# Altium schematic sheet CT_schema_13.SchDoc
size 389 x 385 mm
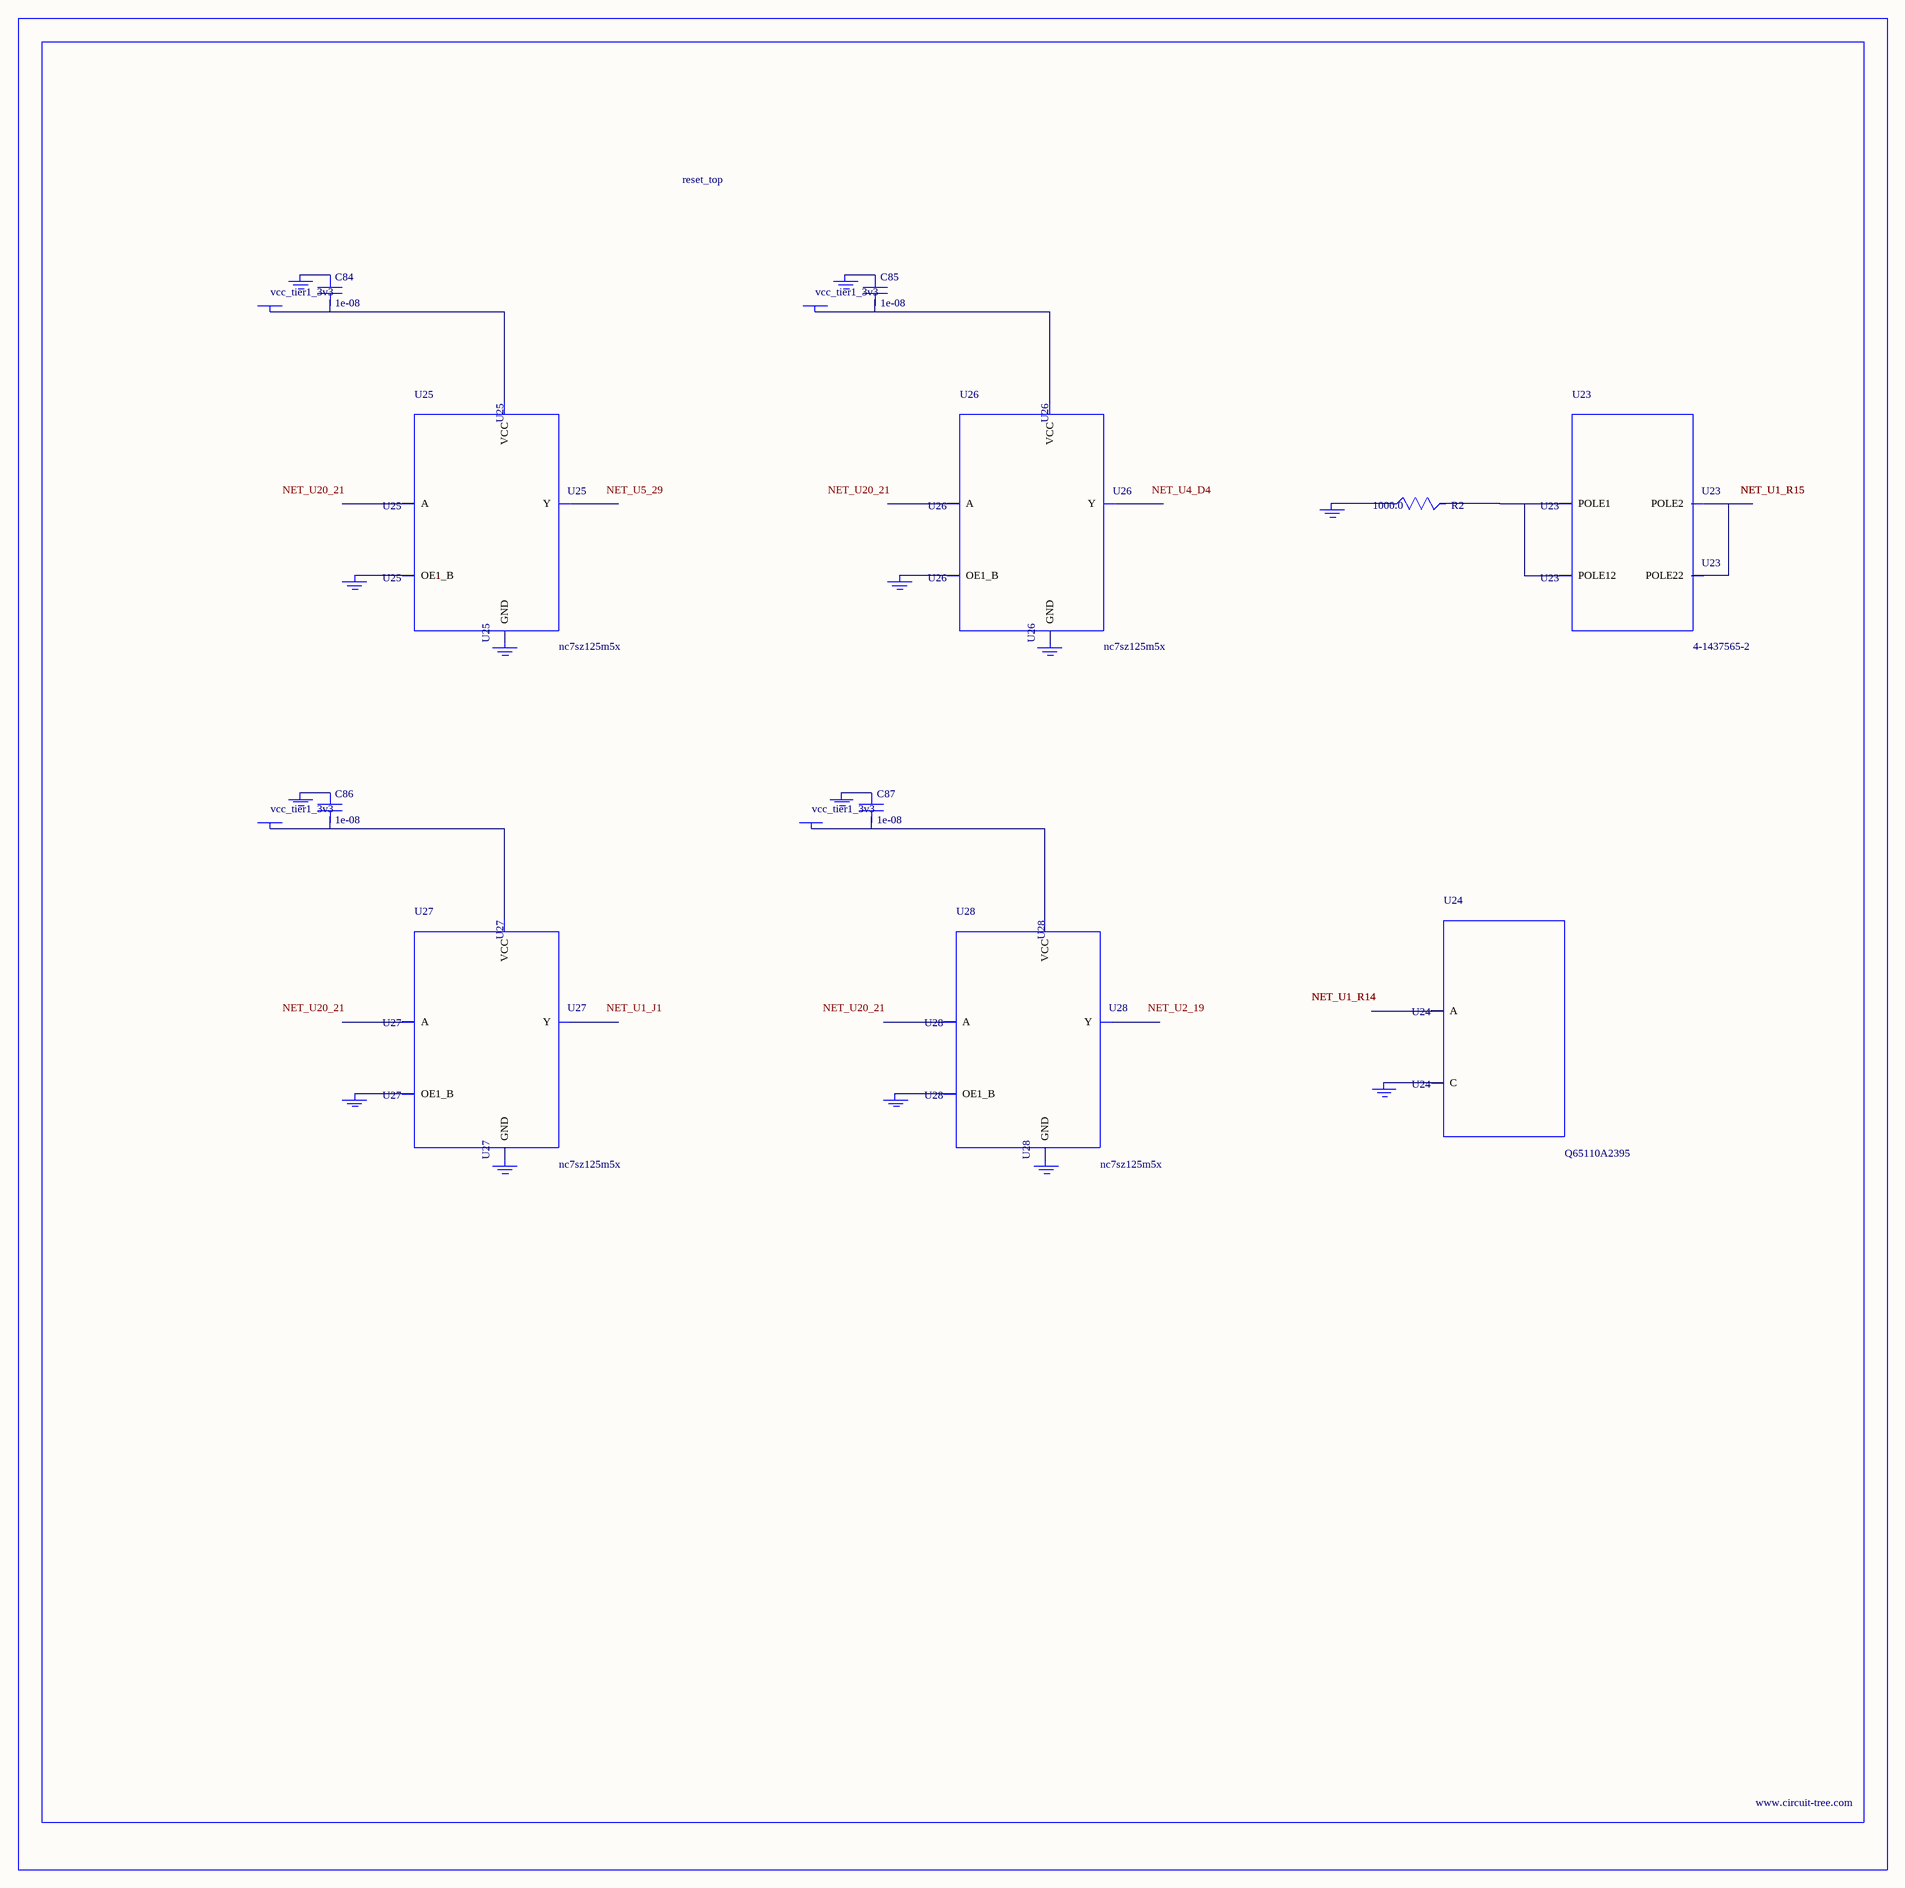
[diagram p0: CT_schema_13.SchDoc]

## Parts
BORDER12  (no value)
C84  1e-08  [C0402]
C85  1e-08  [C0402]
C86  1e-08  [C0402]
C87  1e-08  [C0402]
GND_INSTANCE_12_0  (no value)
GND_INSTANCE_12_1  (no value)
GND_INSTANCE_12_2  (no value)
GND_INSTANCE_12_3  (no value)
GND_INSTANCE_12_4  (no value)
GND_INSTANCE_12_5  (no value)
GND_INSTANCE_12_6  (no value)
GND_INSTANCE_12_7  (no value)
GND_INSTANCE_12_8  (no value)
GND_INSTANCE_12_9  (no value)
GND_INSTANCE_12_10  (no value)
GND_INSTANCE_12_11  (no value)
GND_INSTANCE_12_12  (no value)
GND_INSTANCE_12_13  (no value)
POWER_INSTANCE_12_0  vcc_tier1_3v3
POWER_INSTANCE_12_1  vcc_tier1_3v3
POWER_INSTANCE_12_2  vcc_tier1_3v3
POWER_INSTANCE_12_3  vcc_tier1_3v3
R2  1000.0  [R0603]
U23  4-1437565-2  [SW_4-1437565-2]
U24  Q65110A2395  [LGM67K-G1J2-24-Z]
U25  nc7sz125m5x  [NC7SZ125M5X]
U26  nc7sz125m5x  [NC7SZ125M5X]
U27  nc7sz125m5x  [NC7SZ125M5X]
U28  nc7sz125m5x  [NC7SZ125M5X]

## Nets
NetC84_1: C84.1 GND_INSTANCE_12_2.0(GND)
NetC84_2: C84.2 POWER_INSTANCE_12_0.0(PWR) U25.5(VCC)
NetC85_1: C85.1 GND_INSTANCE_12_5.0(GND)
NetC85_2: C85.2 POWER_INSTANCE_12_1.0(PWR) U26.5(VCC)
NetC86_1: C86.1 GND_INSTANCE_12_8.0(GND)
NetC86_2: C86.2 POWER_INSTANCE_12_2.0(PWR) U27.5(VCC)
NetC87_1: C87.1 GND_INSTANCE_12_11.0(GND)
NetC87_2: C87.2 POWER_INSTANCE_12_3.0(PWR) U28.5(VCC)
NetGND_INSTANCE_12_0_0: GND_INSTANCE_12_0.0(GND) R2.1
NetGND_INSTANCE_12_1_0: GND_INSTANCE_12_1.0(GND) U24.C
NetGND_INSTANCE_12_3_0: GND_INSTANCE_12_3.0(GND) U25.1(OE1_B)
NetGND_INSTANCE_12_4_0: GND_INSTANCE_12_4.0(GND) U25.3(GND)
NetGND_INSTANCE_12_6_0: GND_INSTANCE_12_6.0(GND) U26.1(OE1_B)
NetGND_INSTANCE_12_7_0: GND_INSTANCE_12_7.0(GND) U26.3(GND)
NetGND_INSTANCE_12_9_0: GND_INSTANCE_12_9.0(GND) U27.1(OE1_B)
NetGND_INSTANCE_12_10_0: GND_INSTANCE_12_10.0(GND) U27.3(GND)
NetGND_INSTANCE_12_12_0: GND_INSTANCE_12_12.0(GND) U28.1(OE1_B)
NetGND_INSTANCE_12_13_0: GND_INSTANCE_12_13.0(GND) U28.3(GND)
NetR2_2: R2.2 U23.1(POLE1) U23.2(POLE12)
NetU23_3: U23.3(POLE2) U23.4(POLE22)

Not connected (* = marked no-connect by the designer): U24 A; U25 2(A) 4(Y); U26 2(A) 4(Y); U27 2(A) 4(Y); U28 2(A) 4(Y)

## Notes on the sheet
- Labels drawn without touching a wire or pin: NET_U1_J1, NET_U2_19, NET_U4_D4, NET_U5_29, NET_U20_21

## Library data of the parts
BORDER12 = BORDER_PAGE12
C84-C87 = C0402C103K3RAC
GND_INSTANCE_12_0-GND_INSTANCE_12_13 = GND
POWER_INSTANCE_12_0-POWER_INSTANCE_12_3 = PWR
R2 = RC0603JR-071KL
